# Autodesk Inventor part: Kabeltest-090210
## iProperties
Created: 2009-01
Document SubType Name: Modeling
Designer: R.Schröder
Material: Kabel schwarz
Description: 220V-Leitung Netzteil 1
Density: 1.4 g/cm^3
Mass: 2.55917 g
Surface Area: 24.5486 cm^2
Volume: 1.82798 cm^3
Catalog Web Link: www.das-entwicklungsbuero.de
Part Number: Kabeltest-090210
Manager: Dr.-Ing. Roland Schröder
Company: www.Das-Entwicklungsbuero.de
Category: Konfektionieren
__ICENTER__: VpEWjrdpDpK1mcsYxBHpAaD71i0vtZxVcjkZAQreTbwLsZ5bQ8DTdzysRKY9+fwCKq8Zb+NPj5jSjOPJiLDxNBDsXn/Fw28QeCEHmubG234lFGBly/wj7EwNsOPmX2hh+jiVl9kZkHe3CHk9SRMIdsPaBxf6Au1q
__ICENTER_VERSION__: 4.0.10
d: 3
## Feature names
1. Sweeping7
